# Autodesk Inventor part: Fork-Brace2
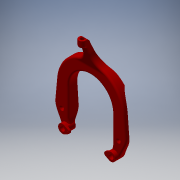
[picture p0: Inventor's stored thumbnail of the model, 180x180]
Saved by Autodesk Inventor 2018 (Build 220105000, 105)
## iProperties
Shininess: 64.0
Length Units: 11272
Angle Units: 11279
Time Units: 11290
Mass Units: 11286
Length Display Precision: 3
Angle Display Precision: 2
Compacted: True
Part Number: Fork-Brace2
Document SubType Name: Modeling
Created: 2003-10
Designer: Autodesk, Inc.
Manufacturer: Standard
Standards Organization: Custom
Mass: 76.099 g
Surface Area: 223.863 cm^2
Volume: 76.099 cm^3
Density: 1 g/cm^3
Material: Generic
Appearance: Red (Flat)_1
Density: 0.0
Volumn: 0.0
Area: 0.0
PropertySet Name: Model Information
Control State: 0
Master: False
Checked Out: False
Translation Standard: STEP AP214DIS
Preprocessor: Autodesk Inventor 8 Pre-Release
Postprocessor: Build: 057b, Release: 8 Pre-Release - Date: Sun 09/16/2003
Sent Units: INCHES
Uncertainty: 1.0000000000000002e-06
Author: Autodesk, Inc.
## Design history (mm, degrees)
feature "Base1"
sketch "Sketch1"
  geometry: L1 (-40.83, 0)-(-40.83, -45.941); L2 (38.288, -53.783)-(39.968, -52.909) reference; L3 (55.902, -40.649)-(48.019, -56.676) reference; L4 (54.945, 5.098)-(58.089, -28.786) reference; L5 (-27.85, 47.638)-(27.85, 47.638) reference; L6 (-58.09, -28.785)-(-54.945, 5.1) reference; L7 (-48.02, -56.678)-(-55.904, -40.648) reference; L8 (-39.968, -52.909)-(-38.288, -53.783) reference; L9 (-40.83, 0)-(-40.83, -45.941) reference; L10 (40.831, -45.941)-(40.831, 0) reference; C1 r 6.35 at (-48.578, -36.14); A1 r 7.302 centre (41.657, -60.261) between (48.019, -56.676) and (38.288, -53.783) reference; A2 r 22.225 centre (35.959, -30.839) between (55.902, -40.649) and (58.184, -30.839) reference; A3 r 22.225 centre (35.959, -30.839) between (58.184, -30.839) and (58.089, -28.786) reference; A4 r 55.181 centre (0, 0) between (54.945, 5.098) and (27.85, 47.638) reference; A5 r 55.182 centre (0, 0) between (-27.85, 47.638) and (-54.945, 5.1) reference; A6 r 22.225 centre (-35.961, -30.839) between (-58.09, -28.785) and (-58.186, -30.839) reference; A7 r 22.225 centre (-35.961, -30.839) between (-58.186, -30.839) and (-55.904, -40.648) reference; A8 r 7.302 centre (-41.657, -60.261) between (-38.288, -53.783) and (-48.02, -56.678) reference; A9 r 28.575 centre (-12.255, -45.941) between (-40.83, -45.941) and (-39.968, -52.909) reference; A10 r 40.83 centre (0, 0) between (40.831, 0) and (-40.83, 0) reference; A11 r 28.575 centre (12.255, -45.941) between (39.968, -52.909) and (40.831, -45.941) reference
  constraints: 2 end point, 1 centre point
  dimensions: "d15" = 7.74707 distance from line of C1.centre L1
hole "Hole1" sketch "Sketch1" at (-48.578, -36.14) diameter "d0" = 3.2512; stored, may be unused: countersink angle "d4" = 90 deg, drill point angle "d6" = 118 deg; dims "d1" = 12.7, "d2" = 7.62, "d3" = 6.35, "d5" = 19.05
workplane "Work Plane1"
sketch "Sketch2"
  geometry: C1 r 3.81 at (-89.044, -0.261) reference
hole "Hole2" sketch "Sketch2" at (-89.044, -0.261) diameter "d7" = 12.7; stored, may be unused: countersink angle "d11" = 0.1 deg, drill point angle "d13" = 0 deg; dims "d8" = 12.7, "d9" = 9.525, "d10" = 6.35, "d12" = 12.7
workaxis "Work Axis1"
workplane "Work Plane2"
mirror "Mirror1"
body "Solid1"
other parameters: "d14" = 0
